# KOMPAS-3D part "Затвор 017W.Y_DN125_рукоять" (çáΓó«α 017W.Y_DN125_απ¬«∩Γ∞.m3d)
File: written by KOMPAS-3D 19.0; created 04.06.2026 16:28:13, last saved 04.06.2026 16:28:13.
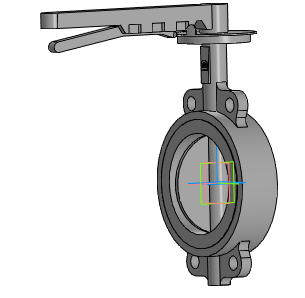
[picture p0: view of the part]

Document properties: Автор: Энергия; Полное имя файла: ..\..\..\3d для проектировщиков\017W разные\x.x Тип 017W.Y(S) Затвор дисковый поворотный межфланцевый\Затвор 017W.Y(S)_DN32-DN350_рукоять\Затвор 017W.Y_DN125_рукоять.a3d

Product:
- Part/product: Затвор 017W.Y_DN125_рукоять
    Масса: 16.5124

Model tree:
1. Операция без истории:1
